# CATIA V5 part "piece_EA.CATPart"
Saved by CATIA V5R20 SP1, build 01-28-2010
Part number: piece_EA
Bounding box of the stored display mesh (mm): x -10 to 28.454, y 20 to 25, z 0 to 68.7
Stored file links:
  C:\Users\Matthieu\Desktop\IAO_2012_mcamard_Catia\piece_EA.CATPart
  C:\Users\Matthieu\Desktop\IAO_Artobolevsky\Artobolevsky_786.CATProduct
  C:\Users\Matthieu\Desktop\IAO_2012_mcamard_Catia\bati.CATPart
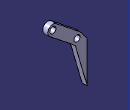
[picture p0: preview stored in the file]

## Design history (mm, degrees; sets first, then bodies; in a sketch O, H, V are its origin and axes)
Set1
  Plane1: linked copy from another document
  Point1 "E": linked copy from another document
  Point2 "A": linked copy from another document
Body1 (main body)
  Sketch1 on Plane1, origin (0, 0, 0), H (-1, 0, 0), V (0, 0, 1)
    construction line L1 (-23.4547, 63.705) -> (0, 45)
    point P1 (-23.4547, 63.705)
    point P2 (0, 45)
    line L2 (-20.3372, 67.6141) -> (3.1175, 48.9091)
    arc A1 centre (-23.4547, 63.705) radius 5 from (-26.5722, 59.7959) to (-20.3372, 67.6141) cw
    circle A2 centre (-23.4547, 63.705) radius 3
    circle A3 centre (0, 45) radius 3
    reference projected point E1 (-23.4547, 63.705) from Point1
    reference projected point E2 (0, 45) from Point2
    line L3 (-26.5722, 59.7959) -> (-8.0192, 45)
    line L4 (3.1175, 48.9091) -> (10, 40)
    line L5 (-8.0192, 45) -> (-1.7496, 40)
    line L6 (-1.7496, 40) -> (10, 0)
    point P9 (10, 0)
    line L7 (10, 40) -> (10, 0)
    distance L1 L2 = 5
    tangency: A1 L2, L3 A1, L5 A1
    coincidence: P1 E1, P2 E2, P9 H
    vertical: L7 V
  Pad1: profile Sketch1, direction (0, 1, 0), length 25, opposite side length -20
